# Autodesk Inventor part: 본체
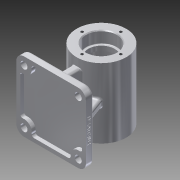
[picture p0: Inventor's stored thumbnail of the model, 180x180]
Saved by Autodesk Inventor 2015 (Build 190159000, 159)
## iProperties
Created: 2019-06
Part Number: 본체
Material: 알루미늄 6061
Document SubType Name: Modeling
Designer: a3
Density: 2.7 g/cm^3
Appearance: 알루미늄 - 평지
Mass: 607.28 g
Surface Area: 624.879 cm^2
Volume: 224.919 cm^3
Author: a3
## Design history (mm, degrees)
sketch "스케치2"
  geometry: L1 (45, 45)-(-45, 45); L2 (-45, 45)-(-45, -45); L3 (-45, -45)-(45, -45); L4 (45, -45)-(45, 45); L5 (45, 45)-(-45, -45); 2 further points
  constraints: 10 end point, 2 parallel, 1 coincident, 1 horizontal, 1 midpoint, 1 perpendicular
  dimensions: "d4" = 90 distance of L3.end L1.start; "d5" = 90 distance of L1.start L1.end
extrude "돌출2" new body sketch "스케치2" distance "d6" = 10; taper "d7" = 0 deg
sketch "스케치3"
  geometry: L1 (65, 40.611)-(65, -47.854); L2 (85, 45)-(85, 30); L3 (85, 30)-(82, 30); L4 (82, 30)-(82, 24); L5 (82, 24)-(90, 24); L6 (90, 24)-(90, -24); L7 (90, -24)-(82, -24); L8 (82, -24)-(82, -30); L9 (82, -30)-(85, -30); L10 (85, -30)-(85, -45); L11 (85, -45)-(97, -45); L12 (97, -45)-(97, 45); L13 (97, 45)-(85, 45); L14 (0, 45)-(0, -45) reference; 1 further point
  constraints: 26 end point, 10 perpendicular, 2 collinear, 2 vertical, 1 horizontal
  dimensions: "d8" = 65 distance between parallel lines of L1 L14; "d9" = 64 diameter of L12 L1; "d10" = 34 diameter of L4 L1; "d11" = 40 diameter of L2 L1; "d12" = 50 diameter of L6 L1; "d13" = 90 distance between parallel lines of L11 L13; "d14" = 45 distance from line of L11 point (0, 0); "d15" = 48 distance between parallel lines of L7 L5; "d16" = 15 distance from line of L3.end L13; "d17" = 15 distance from line of L11 L8.end; "d18" = 24 distance from line of L7 point (0, 0)
revolve "회전1" sketch "스케치3" stored, may be unused: angle "d19" = 90 deg
sketch "스케치4"
  geometry: L1 (-5, -35)-(5, -35); L2 (5, -35)-(5, 35); L3 (5, 35)-(-5, 35); L4 (-5, 35)-(-5, -35); L5 (-5, -35)-(5, 35); 2 further points
  constraints: 10 end point, 2 parallel, 1 coincident, 1 horizontal, 1 midpoint, 1 perpendicular
  dimensions: "d20" = 70 distance of L3.end L1.start; "d21" = 10 distance of L1.start L1.end
extrude "돌출3" join sketch "스케치4" stored distance "d22" = 10; taper "d23" = 0 deg
sketch "스케치5"
  geometry: L1 (0, 0)-(0, 40); L2 (-35, 10)-(-23.058, 42.811); 2 further points
  constraints: 4 end point, 1 vertical, 1 vertical alignment, 3 other
  dimensions: "d33" = 20 deg angle of L2 L1; "d34" = 14.07813 distance from line of point (0, 65) L2; "d35" = 35 distance from line of L2.start L1
feature "리브1" sketch "스케치5" dims "d27" = 1, "d28" = 10, "d29" = 0, "d30" = 0, "d31" = 1, "d32" = 1
fillet "모깎기1" dims "d40" = 10
sketch "스케치6"
  geometry: L1 (22.155, 40)-(-22.155, 40); L2 (-22.155, -40)-(22.155, -40); L3 (40, -22.155)-(40, 22.155); L4 (-40, -40)-(40, 40); L5 (-40, -22.155)-(-40, 22.155); A1 r 10 centre (-35, -35) between (-45, -35) and (-35, -45) reference; A2 r 10 centre (35, -35) between (35, -45) and (45, -35) reference; A3 r 10 centre (35, 35) between (45, 35) and (35, 45) reference; A4 r 10 centre (-35, 35) between (-35, 45) and (-45, 35) reference; A5 r 10 centre (-35, -35) between (-25.119, -36.538) and (-36.538, -25.119); A6 r 10 centre (-35, 35) between (-36.538, 25.119) and (-25.119, 36.538); A7 r 10 centre (35, 35) between (45, 35) and (35, 45) reference; A8 r 10 centre (35, 35) between (25.119, 36.538) and (36.538, 25.119); A9 r 10 centre (35, -35) between (36.538, -25.119) and (25.119, -36.538); A10 r 3 centre (-37, -22.155) between (-40, -22.155) and (-36.538, -25.119); A11 r 3 centre (-22.155, -37) between (-25.119, -36.538) and (-22.155, -40); A12 r 3 centre (22.155, -37) between (22.155, -40) and (25.119, -36.538); A13 r 3 centre (37, -22.155) between (36.538, -25.119) and (40, -22.155); A14 r 3 centre (37, 22.155) between (40, 22.155) and (36.538, 25.119); A15 r 3 centre (22.155, 37) between (25.119, 36.538) and (22.155, 40); A16 r 3 centre (-22.155, 37) between (-22.155, 40) and (-25.119, 36.538); A17 r 3 centre (-37, 22.155) between (-36.538, 25.119) and (-40, 22.155); 10 further points
  constraints: 32 point on circle, 16 tangent, 12 centre point, 10 end point, 8 point on line, 6 equal radius, 5 coincident, 2 parallel, 1 horizontal, 1 midpoint, 1 vertical
  dimensions: "d41" = 20 diameter of A8; "d42" = 20 diameter of A9; "d43" = 20 diameter of A6; "d44" = 20 diameter of A5; "d45" = 45 deg angle of L3 L4; "d47" = 80 distance between parallel lines of L1 L2; "d48" = 5 distance from line of A3.start L3; "d49" = 75 distance from line of A3.start L2; "d50" = 3 radius of A10; "d51" = 3 radius of A11; "d52" = 80 distance between parallel lines of L3 L5; "d53" = 0 distance from line of L4.end L3
extrude "돌출4" cut sketch "스케치6" distance "d54" = 5; taper "d55" = 0 deg
sketch "스케치7"
  geometry: L1 (35, 45)-(-35, 45) reference; L2 (-45, 35)-(-45, -35) reference; L3 (-35, -45)-(35, -45) reference; L4 (45, -35)-(45, 35) reference; L5 (-35, -5)-(-35, 5) reference; L6 (-35, 5)-(-5, 5) reference; L7 (-5, 5)-(-5, 35) reference; L8 (-5, 35)-(5, 35) reference; L9 (5, 35)-(5, 5) reference; L10 (5, 5)-(35, 5) reference; L11 (35, 5)-(35, -5) reference; L12 (35, -5)-(5, -5) reference; L13 (5, -5)-(5, -35) reference; L14 (5, -35)-(-5, -35) reference; L15 (-5, -35)-(-5, -5) reference; L16 (-5, -5)-(-35, -5) reference; A1 r 10 centre (35, 35) between (45, 35) and (35, 45) reference; A2 r 10 centre (-35, 35) between (-35, 45) and (-45, 35) reference; A3 r 10 centre (-35, -35) between (-45, -35) and (-35, -45) reference; A4 r 10 centre (35, -35) between (35, -45) and (45, -35) reference; 1 further point
hole "구멍1" sketch "스케치7" at (-35, 35), (-35, -35), (35, -35), (35, 35) diameter "d56" = 9; stored, may be unused: countersink angle "d60" = 90 deg, drill point angle "d62" = 118 deg; dims "d57" = 6, "d58" = 4, "d59" = 2, "d61" = 8
sketch "스케치8"
  geometry: L1 (0, 0)-(0, 25); C1 r 20 at (0, 0) reference; 1 further point
  constraints: 2 end point, 1 vertical
  dimensions: "d63" = 25 distance of L1.start L1.end
hole "구멍2" sketch "스케치8" at (0, 25) diameter "d64" = 3.459; stored, may be unused: countersink angle "d68" = 90 deg, drill point angle "d70" = 118 deg; dims "d65" = 7, "d66" = 4, "d67" = 2, "d69" = 9
node "작업 평면1"
sketch "스케치9"
  geometry: C1 r 5 at (0, 0); 1 further point
  constraints: 1 centre point, 1 coincident
  dimensions: "d76" = 10 diameter of C1
extrude "돌출5" join sketch "스케치9" stored distance "d77" = 5; taper "d78" = 0 deg
sketch "스케치10"
  geometry: C1 r 5 at (0, 0) reference; 1 further point
hole "구멍3" sketch "스케치10" at (0, 0) diameter "d79" = 4.917; stored, may be unused: countersink angle "d83" = 90 deg, drill point angle "d85" = 118 deg; dims "d80" = 12, "d81" = 4, "d82" = 2, "d84" = 17.1
fillet "모깎기2" dims "d86" = 3
fillet "모깎기3" dims "d87" = 3
fillet "모깎기4" dims "d88" = 2
fillet "모깎기5" dims "d89" = 0.6
fillet "모깎기7" dims "d91" = 0.6
chamfer "모따기1" distance "d92" = 1; stored, may be unused: second distance "d93" = 2, angle "d94" = 45 deg
sketch "스케치11"
  geometry: L1 (-10, 7)-(-10, 0) reference; L2 (0, 0)-(-10, 0) reference; 2 further points
  constraints: 1 other
  dimensions: "d95" = 45 distance from line of point (35, 4) L1; "d97" = 4 distance from line of point (35, 4) L2
feature "엠보싱1" sketch "스케치11" dims "d4" = 90, "d5" = 90, "d8" = 65, "d9" = 64, "d10" = 34, "d11" = 40, "d12" = 50, "d13" = 90, "d14" = 45, "d15" = 48, "d16" = 15, "d17" = 15, "d18" = 24, "d98" = 0.5, "d99" = 0
fillet "모깎기8" dims "d100" = 3
node "솔리드2"
mirror "대칭1"
pattern_circular "원형 패턴1" dims angle "d72" = 360 deg
mirror "대칭2"
node "투영된 루프1"
node "투영된 루프2"
other parameters: "d26" = 110 deg
